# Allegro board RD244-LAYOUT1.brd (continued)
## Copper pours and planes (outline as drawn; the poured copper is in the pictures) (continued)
SIG008126 on TOP: 211.75,5.75 211.64,5.79 211.6,5.9 211.6,8.14 211.61,8.2 211.64,8.24 213.01,9.61 213.05,9.64 213.11,9.65 215.29,9.65 215.35,9.64 215.39,9.61 216.55,8.45 217.65,8.45 218.65,9.45 218.69,9.48 218.75,9.49 219.66,9.49 219.72,9.48 219.76,9.45 220.01,9.2 220.04,9.16 220.05,9.1 220.05,8.22 220.04,8.16 220.01,8.12 218.68,6.79 218.64,6.76 218.58,6.75 216.95,6.75 215.99,5.79 215.95,5.76 215.89,5.75
SIG008126 on BOTTOM: 209.5,1.7 209.39,1.71 209.28,1.75 209.12,1.83 209.09,1.85 201.83,1.85 201.5,1.78 201.43,1.77 201.2,2 201.43,2.23 201.5,2.22 201.83,2.15 208.44,2.15 208.59,2.31 208.61,2.32 208.64,2.34 209.28,2.65 209.39,2.69 209.5,2.7 210.28,2.7 210.78,2.2 210.28,1.7
SIG008126 on BOTTOM: 213.09,6.89 212.94,7.2 212.94,7.21 213.25,8 213.25,8.3 212.89,8.66 212.86,8.7 212.85,8.76 212.85,8.89 212.86,8.95 212.89,8.99 212.96,9.06 213,9.09 213.06,9.1 213.34,9.1 213.4,9.09 213.44,9.06 213.71,8.79 213.74,8.75 213.75,8.69 213.75,8 214.06,7.21 214.06,7.2 213.91,6.89 213.59,7.03 213.5,7.27
SIG008132 on TOP: 211.86,13.06 211.75,13.1 211.71,13.21 211.71,16.24 211.75,16.35 211.86,16.39 213.61,16.39 213.72,16.35 213.76,16.24 213.76,13.21 213.72,13.1 213.61,13.06
SIG008132 on BOTTOM: 214.35,16.43 214.24,16.47 214.2,16.58 214.2,17.27 214.21,17.33 214.24,17.37 214.63,17.76 214.67,17.79 214.73,17.8 216.15,17.8 216.26,17.76 216.3,17.65 216.3,16.58 216.26,16.47 216.15,16.43
SIGN355 on TOP: 193.32,101.91 193.26,101.92 193.22,101.95 192.88,102.29 192.85,102.33 192.84,102.39 192.84,103.84 192.85,103.9 192.88,103.94 193.04,104.1 193.08,104.13 193.14,104.14 194.46,104.14 194.52,104.13 194.56,104.1 195.16,103.5 195.19,103.46 195.2,103.4 195.2,102.59 195.19,102.53 195.16,102.49 194.62,101.95 194.58,101.92 194.52,101.91
SIGN355 on BOTTOM: 185.93,52.3 185.8,52.32 185.57,52.45 183.85,54.17 183.82,54.21 183.81,54.27 183.81,105.08 167.09,121.8 157.65,121.8 157.54,121.84 157.5,121.95 157.5,143.55 157.54,143.66 157.65,143.7 168.4,143.7 168.75,143.55 168.9,143.2 168.9,136.06 168.89,136 168,134.64 167.7,133.1 167.7,131.3 168.9,128.4 171.8,127.2 174.54,127.2 174.6,127.19 174.64,127.16 189.79,112.01 189.82,111.97 189.83,111.91 189.83,105.93 191.61,104.15 194.46,104.15 194.52,104.14 194.56,104.11 195.16,103.51 195.19,103.47 195.2,103.41 195.2,102.6 195.19,102.54 195.16,102.5 194.63,101.97 194.59,101.94 194.53,101.93 191.67,101.93 189.82,100.08 189.82,61.86 194.08,57.6 218.2,57.6 218.55,57.45 218.7,57.1 218.7,54.61 218.66,54.42 216.75,52.45 216.58,52.34 216.39,52.3
SIGN355 on CONDUCTIVE5: 185.76,52.3 185.72,52.31 185.69,52.33 183.84,54.18 183.82,54.21 183.81,54.25 183.81,105.16 167.17,121.8 157.6,121.8 157.53,121.83 157.5,121.9 157.5,143.6 157.53,143.67 157.6,143.7 168.4,143.7 168.75,143.55 168.9,143.2 168.9,134.8 168.9,134.78 168.56,133.96 168.45,133.1 168.45,131.3 169.57,128.8 172.18,127.97 172.19,127.97 173.82,127.97 173.86,127.96 173.89,127.94 189.84,111.99 189.86,111.96 189.87,111.92 189.87,105.89 191.59,104.18 194.44,104.18 194.48,104.17 194.51,104.15 195.19,103.47 195.21,103.44 195.22,103.4 195.22,102.52 195.21,102.48 195.19,102.45 194.72,101.98 194.69,101.96 194.65,101.95 191.69,101.95 189.85,100.11 189.85,61.94 194.19,57.6 218.2,57.6 218.55,57.45 218.7,57.1 218.7,54.61 218.66,54.42 218.55,54.25 216.75,52.45 216.64,52.37 216.39,52.3
SIGN356 on TOP: 235.74,40.93 235.74,41.37 235.18,41.68 235.08,42.02 235.42,42.11 236.71,41.4 238.75,41.4 240.05,42.7 240.05,44.95 239.86,45.59 239.84,45.66 239.84,45.72 239.84,46.05 239.97,46.38 240.3,46.51 243.8,46.51 243.91,46.47 243.95,46.36 243.95,43.5 243.91,43.39 243.8,43.35 241.4,43.35 239.03,40.97 238.95,40.92 238.85,40.9 236.71,40.9 235.42,40.19 235.08,40.28 235.18,40.62
SS/EN on TOP: 263.84,8.24 263.67,8.17 263.56,8.32 263.56,8.34 263.54,8.33 263.4,8.45 263.47,8.62 263.82,8.81 264.35,9.34 264.35,9.82 264.28,10.15 264.27,10.2 264.27,10.38 264.36,10.55 264.55,10.59 264.88,10.53 265.11,10.53 265.35,10.76 265.35,11.3 265.35,11.33 265.57,12.27 265.58,12.3 265.61,12.34 265.63,12.36 265.67,12.38 265.8,12.36 265.87,12.23 265.86,12.2 265.77,11.79 265.99,11.57 266.4,11.66 266.48,11.66 266.54,11.62 266.57,11.57 266.58,11.52 266.55,11.42 266.47,11.37 265.74,11.2 265.65,11.11 265.65,10.7 265.64,10.64 265.28,10.27 265.23,10.24 265.18,10.22 264.88,10.22 264.73,10.19 264.72,10.15 264.65,9.82 264.65,9.28 264.64,9.22 264.61,9.17 264.03,8.6
SS/EN on BOTTOM: 264.6,7.78 264.57,7.78 264.27,7.83 264,7.83 263.94,7.84 263.89,7.87 263.82,7.94 263.47,8.13 263.43,8.16 263.4,8.21 263.39,8.27 263.39,8.29 263.34,8.36 263.34,8.45 263.45,8.84 263.45,9.94 261.81,11.57 261.39,11.57 261.28,11.62 261.24,11.72 261.24,12.29 261.28,12.4 261.39,12.44 261.63,12.44 261.72,12.42 261.77,12.35 261.98,11.83 263.74,10.06 263.75,10 263.75,8.84 263.86,8.48 264.03,8.15 264.06,8.12 264.27,8.12 264.57,8.17 264.6,8.18 265.36,8.18 265.56,7.97 265.36,7.78

Small or netless copper shapes (teardrops, artwork), in the pictures only: 75 on TOP, 176 on BOTTOM, 5 on CONDUCTIVE2, 48 on CONDUCTIVE3, 22 on CONDUCTIVE4, 1 on CONDUCTIVE5

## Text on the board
Ref Des/Silkscreen Bottom: 1 | 2 | 6 | 7 | 3 | 4 | 5
Ref Des/Silkscreen Top: S | 1 | G | D | A | C | 2 | 6 | 7 | 3 | 4 | 5 | 8 | P4 | P3 | P2 | P1 | 14 | 12
SYMBOL-1-TOP: S | 1 | G | D | A | C | 2 | 6 | 7 | 3 | 4 | 5 | 8 | P4 | P3 | P2 | P1 | 14 | 12
SYMBOL-2-TOP: C3 | C54 | RV1 | L1 | L2 | R3 | C6 | R4 | RY1 | R305 | C9 | IC301 | C303 | DP303 | L52 | DP301 | D303 | DP302 | DP51 | DP53 | DP55 | DP52 | C51 | C68 | C69 | DP57 | DP56 | DP54 | A101 | A102 | A51 | L51 | C52 | F401 | C53 | C401 | D102 | DP404 | DP306 | C408 | DP402 | R315 | T201 | C404 | DP305 | T101 | DP401 | D401 | R313 | C310 | DP403 | T151 | R316 | Q301 | C414 | DS301 | D251 | DP157 | CN153 | CN203 | CN151 | D451 | C451 | CN201 | DP451 | DP256 | D207 | L151 | R264 | R351 | L201 | Q351 | R269 | CN202 | DP251 | C503 | TB502 | DP257 | C506 | DP260 | R504 | D208 | CN152 | DP501 | DP258 | R252 | R253 | R254 | R255 | DP261 | Q501 | C501 | CN501 | TB501 | Q502 | DP502 | Q503 | C502 | C205 | C204 | R208 | R210 | DP503 | CN502 | PFC_OFF | GDB | PN | GDA | PFCOUT | A | CS | VDD | BK-S | CL-F | BK-F | VCC18R0_1 | OUTE | CL-S | OUTF | Q501(G) | LGND | RD244 Main unit | SGB009501000 | SAA009501010 | VPSFB_OUT | VOUT | TB1 | CN1 | C2 | C1 | C5 | C7 | C8 | C4 | FH2 | FH1 | D55 | C302 | R306 | C305 | R307 | C304 | D302 | D304 | R308 | R69 | L101 | CN106 | CN104 | CN103 | CN102 | CN105 | CN101 | D101 | R404 | R405 | R406 | R402 | R403 | C308 | C307 | C306 | Q401 | IC302 | DP304 | R314 | R401 | C402 | D403 | T401 | C403 | R312 | R317 | R251 | DP252 | DP254 | DP253 | DP207 | DP255 | DP259 | R274 | R275 | R276 | C505 | R263 | R352 | R265 | R353 | R273 | R268 | OUTA1 | OUTC1 | OUTB1 | OUTD1 | TU-S | TU-F | S | 1 | G | D | C | 2 | 3 | 5 | 4 | 8 | FOR CONTINUED PROTECTION AGAINST RISK OF FIRE. | 6 | P4 | P3 | P2 | P1 | 7 | 12 | 14 | REPLACE ONLY WITH SAME TYPE | Heatsink | PSFB | (A&B) | (C&D) | PFC | 250V T30AH | CAUTION
SYMBOL-2-BOTTOM: IC1 | R304 | R303 | R302 | R301 | D51 | D52 | D53 | D54 | R53 | D1 | R54 | C66 | R68 | C64 | R67 | R60 | R63 | R59 | IC51 | R74 | R57 | R51 | R52 | R65 | C63 | C62 | R66 | C409 | C410 | R413 | R416 | R409 | IC402 | IC401 | C405 | R408 | D402 | R309 | C412 | C413 | R310 | R311 | IC303 | R354 | R357 | R360 | R363 | R365 | DP153 | R364 | R204 | D153 | R154 | D203 | DP151 | R454 | DP202 | Q201 | Q151 | IC451 | DP201 | R355 | R358 | R361 | DP203 | R151 | Q152 | R201 | Q202 | C255 | R261 | C253 | C252 | R452 | DP205 | R262 | C251 | DP155 | Q153 | Q203 | R207 | IC251 | R157 | Q154 | R257 | R267 | C254 | R501 | R502 | R503 | Q204 | IC151 | D156 | Q155 | C256 | IC201 | D206 | DP154 | Q205 | C504 | DP204 | DP156 | R259 | DP206 | Q206 | Q156 | R271 | C258 | R258 | R209 | C510 | Q504 | R159 | C509 | R505 | R506 | C507 | Q506 | Q507 | Q151(S) | Q201(G) | Q151(D) | Q201(D) | Q201(S) | Q205(G) | Q155(G) | Q155(D) | Q155(S) | Q205(D) | Q205(S) | R2 | R1 | C301 | D2 | C11 | R64 | D56 | C65 | C67 | C60 | C59 | C61 | C58 | R58 | R70 | R72 | R55 | R71 | C70 | C57 | C56 | C55 | R73 | R56 | R61 | R62 | R101 | R102 | C411 | D405 | R415 | R414 | D404 | IC403 | C407 | R412 | C309 | R407 | R417 | R410 | R411 | C406 | D201 | R202 | D202 | R203 | R362 | R359 | R356 | C351 | D151 | R152 | D157 | DP152 | R451 | C453 | D152 | R153 | C452 | R256 | R453 | C152 | C201 | C151 | R260 | C153 | C202 | C203 | R155 | D154 | D204 | R205 | R266 | R156 | D155 | R206 | D205 | R277 | C257 | R278 | R279 | R281 | R283 | R280 | R282 | D158 | R272 | C511 | R284 | R270 | C508 | C155 | C154 | R160 | R158 | Q151(G) | 1 | 2 | 6 | 7 | 3 | 4 | 5
User.5: 1 | 2 | 6 | 7 | 3 | 4 | 5
